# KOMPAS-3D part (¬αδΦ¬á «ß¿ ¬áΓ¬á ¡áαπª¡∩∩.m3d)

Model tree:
1. Эскиз:1
2. Операция выдавливания:1
     Расстояние 1 = 1
3. Эскиз:2
4. Операция выдавливания:2
     Расстояние 1 = 2
5. Эскиз:3
6. Отверстие:1
7. Скругление:1
     Радиус = 2
8. Скругление:2
     Радиус = 2
9. Скругление:3
     Радиус = 0.4
10. Эскиз:4
11. Операция выдавливания:3
     Расстояние 1 = 0.2
12. Массив по концентрической сетке:1  (with: Операция выдавливания:3)  (labels: Экземпляр ( 1, 1 ); Экземпляр ( 1, 2 ); Экземпляр ( 1, 3 ); Экземпляр ( 1, 4 ))
     N 2 = 6; Шаг 2 = 360
13. Эскиз:5
14. Операция выдавливания:4
     Расстояние 1 = 0.3
15. Массив по концентрической сетке:2  (with: Операция выдавливания:4)  (labels: Экземпляр ( 1, 1 ); Экземпляр ( 1, 2 ); Экземпляр ( 1, 3 ); Экземпляр ( 1, 4 ))
     N 2 = 6; Шаг 2 = 360
16. Эскиз:6
17. Операция выдавливания:5
     Расстояние 1 = 1
18. Массив по концентрической сетке:3  (with: Операция выдавливания:5)  (labels: Экземпляр ( 1, 1 ); Экземпляр ( 1, 2 ); Экземпляр ( 1, 3 ); Экземпляр ( 1, 4 ))
     N 2 = 6; Шаг 2 = 360
19. Скругление:4
     Радиус = 0.3
20. Скругление:5
     Радиус = 0.3

Referenced files in C:\Program Files\ASCON\KOMPAS-3D V13 Home\Sys\: holelib.lfr
Referenced files in C:\Program Files\ASCON\KOMPAS-3D V12\Sys\: holelib.lfr
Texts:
  крышка катка наружняя
  крышка оси катка т90 наружняя для точеного
  Сплав АЛ8  ГОСТ 1583-93
  Отверстие 02
  (вариант 2)
  Номер 1
  Номер 2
